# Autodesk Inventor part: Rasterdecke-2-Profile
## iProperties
Created: 2008-01
Part Number: Rasterdecke-2-Profile
Document SubType Name: Modeling
Designer: sec
Density: 1 g/cm^3
Author: sec
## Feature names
1. Extrusion1
2. Wandstärke1
3. Sweeping1
